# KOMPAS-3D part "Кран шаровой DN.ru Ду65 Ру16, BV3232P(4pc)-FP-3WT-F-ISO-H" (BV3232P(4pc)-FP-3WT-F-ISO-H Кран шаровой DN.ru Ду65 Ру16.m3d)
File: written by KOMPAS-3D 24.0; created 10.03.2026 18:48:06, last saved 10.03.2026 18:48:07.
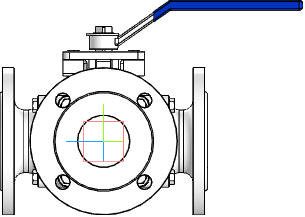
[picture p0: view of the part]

Document properties: Автор: R2D2; Полное имя файла: E:\Работа\Зайцев\BV3232P(4pc)-FP-3WT-F-ISO-H Кран шаровой DN.ru Ду15-100 Ру16\DN65\BV3232P(4pc)-FP-3WT-F-ISO-H Кран шаровой DN.ru Ду65 Ру16.m3d

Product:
- Part/product: Кран шаровой DN.ru Ду65 Ру16  | designation BV3232P(4pc)-FP-3WT-F-ISO-H
    Масса: 26.5
    Раздел спецификации: Прочие изделия
    Примечание: D160-36352

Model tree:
1. Операция без истории:1

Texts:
  BV3232P(4pc)-FP-3WT-F-ISO-H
